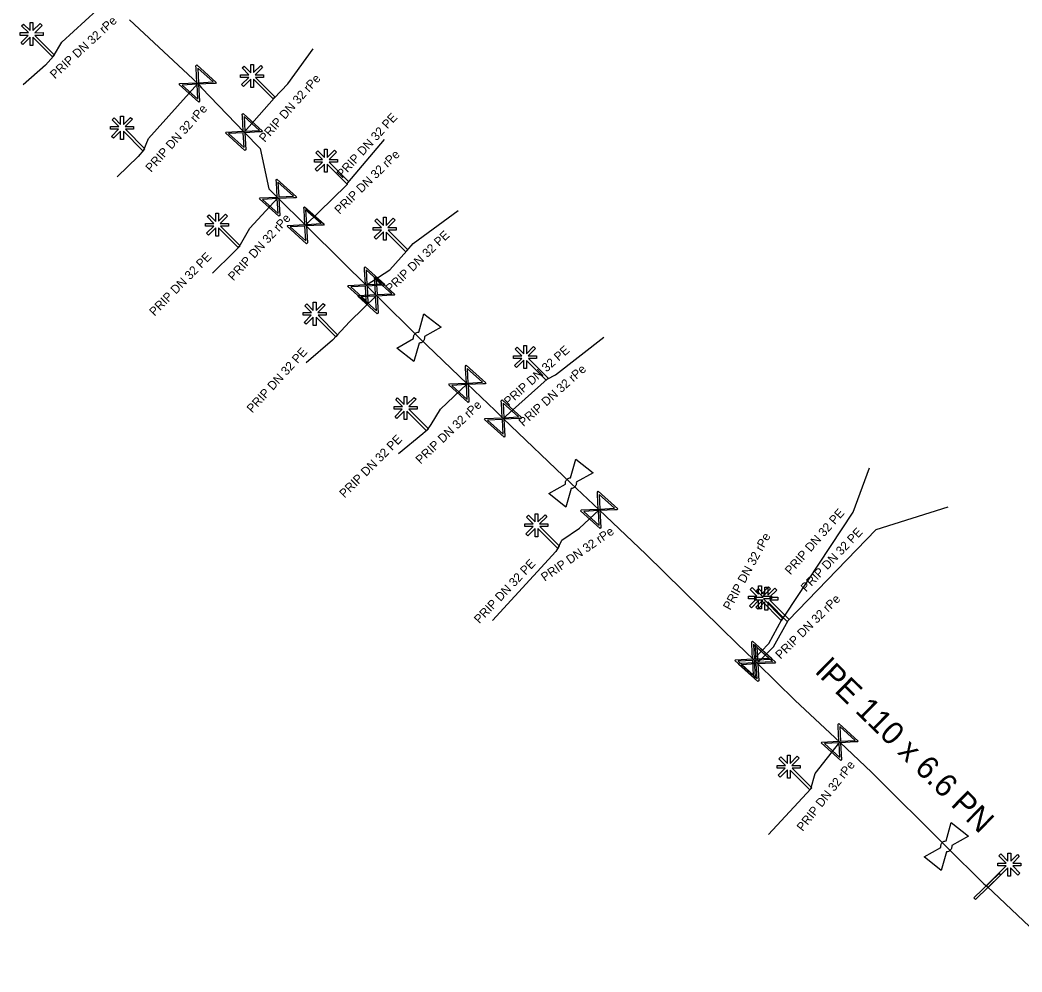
# Model space of a CAD drawing. Extents: x -643842 to -636370, y -1119190 to -1110210.
# Drawn here: x -640918.7 to -640861.5, y -1114875.7 to -1114821.3 of the extents above; entities that cross this region are included whole.
import ezdxf

# ---------------------------------------------------------------- set-up
doc = ezdxf.new("R2010")
doc.units = 0
for name, color, linetype in [('2', 7, 'Continuous'), ('22', 7, 'Continuous'), ('Default', 7, 'Continuous'), ('Level 16', 7, 'Continuous'), ('Level 20', 7, 'Continuous'), ('Level 21', 7, 'Continuous'), ('Level 23', 7, 'Continuous'), ('Level 28', 7, 'Continuous')]:
    doc.layers.add(name, color=color, linetype=linetype)

msp = doc.modelspace()

# ---------------------------------------------------------------- linework, layer by layer
at = {"layer": '2'}
for points in [[(-640918.238, -1114822.055), (-640918.619, -1114821.673), (-640918.508, -1114821.563), (-640918.131, -1114821.941), (-640918.131, -1114821.473), (-640917.974, -1114821.474), (-640917.974, -1114821.939), (-640917.566, -1114821.532), (-640917.456, -1114821.643), (-640917.871, -1114822.057), (-640917.397, -1114822.056), (-640917.397, -1114822.212), (-640917.861, -1114822.212), (-640916.743, -1114823.333), (-640916.854, -1114823.443), (-640917.975, -1114822.319), (-640917.975, -1114822.791), (-640918.131, -1114822.79), (-640918.131, -1114822.316), (-640918.545, -1114822.729), (-640918.656, -1114822.618), (-640918.248, -1114822.212), (-640918.712, -1114822.211), (-640918.712, -1114822.055), (-640918.238, -1114822.055)], [(-640905.648, -1114824.455), (-640906.029, -1114824.073), (-640905.918, -1114823.963), (-640905.541, -1114824.341), (-640905.541, -1114823.873), (-640905.384, -1114823.874), (-640905.384, -1114824.339), (-640904.976, -1114823.932), (-640904.866, -1114824.043), (-640905.281, -1114824.457), (-640904.807, -1114824.456), (-640904.807, -1114824.612), (-640905.271, -1114824.612), (-640904.153, -1114825.733), (-640904.264, -1114825.843), (-640905.385, -1114824.719), (-640905.385, -1114825.191), (-640905.541, -1114825.19), (-640905.541, -1114824.716), (-640905.955, -1114825.129), (-640906.066, -1114825.018), (-640905.658, -1114824.612), (-640906.122, -1114824.611), (-640906.122, -1114824.455), (-640905.648, -1114824.455)], [(-640913.078, -1114827.415), (-640913.459, -1114827.033), (-640913.348, -1114826.923), (-640912.971, -1114827.301), (-640912.971, -1114826.833), (-640912.814, -1114826.834), (-640912.814, -1114827.299), (-640912.406, -1114826.892), (-640912.296, -1114827.003), (-640912.711, -1114827.417), (-640912.237, -1114827.416), (-640912.237, -1114827.572), (-640912.701, -1114827.572), (-640911.583, -1114828.693), (-640911.694, -1114828.803), (-640912.815, -1114827.679), (-640912.815, -1114828.151), (-640912.971, -1114828.15), (-640912.971, -1114827.676), (-640913.385, -1114828.089), (-640913.496, -1114827.978), (-640913.088, -1114827.572), (-640913.552, -1114827.571), (-640913.552, -1114827.415), (-640913.078, -1114827.415)], [(-640901.438, -1114829.295), (-640901.819, -1114828.913), (-640901.708, -1114828.803), (-640901.331, -1114829.181), (-640901.331, -1114828.713), (-640901.174, -1114828.714), (-640901.174, -1114829.179), (-640900.766, -1114828.772), (-640900.656, -1114828.883), (-640901.071, -1114829.297), (-640900.597, -1114829.296), (-640900.597, -1114829.452), (-640901.061, -1114829.452), (-640899.943, -1114830.573), (-640900.054, -1114830.683), (-640901.175, -1114829.559), (-640901.175, -1114830.031), (-640901.331, -1114830.03), (-640901.331, -1114829.556), (-640901.745, -1114829.969), (-640901.856, -1114829.858), (-640901.448, -1114829.452), (-640901.912, -1114829.451), (-640901.912, -1114829.295), (-640901.438, -1114829.295)], [(-640907.648, -1114832.945), (-640908.029, -1114832.563), (-640907.918, -1114832.453), (-640907.541, -1114832.831), (-640907.541, -1114832.363), (-640907.384, -1114832.364), (-640907.384, -1114832.829), (-640906.976, -1114832.422), (-640906.866, -1114832.533), (-640907.281, -1114832.947), (-640906.807, -1114832.946), (-640906.807, -1114833.102), (-640907.271, -1114833.102), (-640906.153, -1114834.223), (-640906.264, -1114834.333), (-640907.385, -1114833.209), (-640907.385, -1114833.681), (-640907.541, -1114833.68), (-640907.541, -1114833.206), (-640907.955, -1114833.619), (-640908.066, -1114833.508), (-640907.658, -1114833.102), (-640908.122, -1114833.101), (-640908.122, -1114832.945), (-640907.648, -1114832.945)], [(-640898.078, -1114833.175), (-640898.459, -1114832.793), (-640898.348, -1114832.683), (-640897.971, -1114833.061), (-640897.971, -1114832.593), (-640897.814, -1114832.594), (-640897.814, -1114833.059), (-640897.406, -1114832.652), (-640897.296, -1114832.763), (-640897.711, -1114833.177), (-640897.237, -1114833.176), (-640897.237, -1114833.332), (-640897.701, -1114833.332), (-640896.583, -1114834.453), (-640896.694, -1114834.563), (-640897.815, -1114833.439), (-640897.815, -1114833.911), (-640897.971, -1114833.91), (-640897.971, -1114833.436), (-640898.385, -1114833.849), (-640898.496, -1114833.738), (-640898.088, -1114833.332), (-640898.552, -1114833.331), (-640898.552, -1114833.175), (-640898.078, -1114833.175)], [(-640902.078, -1114838.035), (-640902.459, -1114837.653), (-640902.348, -1114837.543), (-640901.971, -1114837.921), (-640901.971, -1114837.453), (-640901.814, -1114837.454), (-640901.814, -1114837.919), (-640901.406, -1114837.512), (-640901.296, -1114837.623), (-640901.711, -1114838.037), (-640901.237, -1114838.036), (-640901.237, -1114838.192), (-640901.701, -1114838.192), (-640900.583, -1114839.313), (-640900.694, -1114839.423), (-640901.815, -1114838.299), (-640901.815, -1114838.771), (-640901.971, -1114838.77), (-640901.971, -1114838.296), (-640902.385, -1114838.709), (-640902.496, -1114838.598), (-640902.088, -1114838.192), (-640902.552, -1114838.191), (-640902.552, -1114838.035), (-640902.078, -1114838.035)], [(-640890.068, -1114840.505), (-640890.449, -1114840.123), (-640890.338, -1114840.013), (-640889.961, -1114840.391), (-640889.961, -1114839.923), (-640889.804, -1114839.924), (-640889.804, -1114840.389), (-640889.396, -1114839.982), (-640889.286, -1114840.093), (-640889.701, -1114840.507), (-640889.227, -1114840.506), (-640889.227, -1114840.662), (-640889.691, -1114840.662), (-640888.573, -1114841.783), (-640888.684, -1114841.893), (-640889.805, -1114840.769), (-640889.805, -1114841.241), (-640889.961, -1114841.24), (-640889.961, -1114840.766), (-640890.375, -1114841.179), (-640890.486, -1114841.068), (-640890.078, -1114840.662), (-640890.542, -1114840.661), (-640890.542, -1114840.505), (-640890.068, -1114840.505)], [(-640896.888, -1114843.405), (-640897.269, -1114843.023), (-640897.158, -1114842.913), (-640896.781, -1114843.291), (-640896.781, -1114842.823), (-640896.624, -1114842.824), (-640896.624, -1114843.289), (-640896.216, -1114842.882), (-640896.106, -1114842.993), (-640896.521, -1114843.407), (-640896.047, -1114843.406), (-640896.047, -1114843.562), (-640896.511, -1114843.562), (-640895.393, -1114844.683), (-640895.504, -1114844.793), (-640896.625, -1114843.669), (-640896.625, -1114844.141), (-640896.781, -1114844.14), (-640896.781, -1114843.666), (-640897.195, -1114844.079), (-640897.306, -1114843.968), (-640896.898, -1114843.562), (-640897.362, -1114843.561), (-640897.362, -1114843.405), (-640896.888, -1114843.405)], [(-640889.418, -1114850.105), (-640889.799, -1114849.723), (-640889.688, -1114849.613), (-640889.311, -1114849.991), (-640889.311, -1114849.523), (-640889.154, -1114849.524), (-640889.154, -1114849.989), (-640888.746, -1114849.582), (-640888.636, -1114849.693), (-640889.051, -1114850.107), (-640888.577, -1114850.106), (-640888.577, -1114850.262), (-640889.041, -1114850.262), (-640887.923, -1114851.383), (-640888.034, -1114851.493), (-640889.155, -1114850.369), (-640889.155, -1114850.841), (-640889.311, -1114850.84), (-640889.311, -1114850.366), (-640889.725, -1114850.779), (-640889.836, -1114850.668), (-640889.428, -1114850.262), (-640889.892, -1114850.261), (-640889.892, -1114850.105), (-640889.418, -1114850.105)], [(-640876.658, -1114854.225), (-640877.039, -1114853.843), (-640876.928, -1114853.733), (-640876.551, -1114854.111), (-640876.551, -1114853.643), (-640876.394, -1114853.644), (-640876.394, -1114854.109), (-640875.986, -1114853.702), (-640875.876, -1114853.813), (-640876.291, -1114854.227), (-640875.817, -1114854.226), (-640875.817, -1114854.382), (-640876.281, -1114854.382), (-640875.163, -1114855.503), (-640875.274, -1114855.613), (-640876.395, -1114854.489), (-640876.395, -1114854.961), (-640876.551, -1114854.96), (-640876.551, -1114854.486), (-640876.965, -1114854.899), (-640877.076, -1114854.788), (-640876.668, -1114854.382), (-640877.132, -1114854.381), (-640877.132, -1114854.225), (-640876.658, -1114854.225)], [(-640876.298, -1114854.295), (-640876.679, -1114853.913), (-640876.568, -1114853.803), (-640876.191, -1114854.181), (-640876.191, -1114853.713), (-640876.034, -1114853.714), (-640876.034, -1114854.179), (-640875.626, -1114853.772), (-640875.516, -1114853.883), (-640875.931, -1114854.297), (-640875.457, -1114854.296), (-640875.457, -1114854.452), (-640875.921, -1114854.452), (-640874.803, -1114855.573), (-640874.914, -1114855.683), (-640876.035, -1114854.559), (-640876.035, -1114855.031), (-640876.191, -1114855.03), (-640876.191, -1114854.556), (-640876.605, -1114854.969), (-640876.716, -1114854.858), (-640876.308, -1114854.452), (-640876.772, -1114854.451), (-640876.772, -1114854.295), (-640876.298, -1114854.295)], [(-640875.018, -1114863.895), (-640875.399, -1114863.513), (-640875.288, -1114863.403), (-640874.911, -1114863.781), (-640874.911, -1114863.313), (-640874.754, -1114863.314), (-640874.754, -1114863.779), (-640874.346, -1114863.372), (-640874.236, -1114863.483), (-640874.651, -1114863.897), (-640874.177, -1114863.896), (-640874.177, -1114864.052), (-640874.641, -1114864.052), (-640873.523, -1114865.173), (-640873.634, -1114865.283), (-640874.755, -1114864.159), (-640874.755, -1114864.631), (-640874.911, -1114864.63), (-640874.911, -1114864.156), (-640875.325, -1114864.569), (-640875.436, -1114864.458), (-640875.028, -1114864.052), (-640875.492, -1114864.051), (-640875.492, -1114863.895), (-640875.018, -1114863.895)], [(-640862.165, -1114869.372), (-640861.783, -1114868.991), (-640861.673, -1114869.102), (-640862.051, -1114869.479), (-640861.583, -1114869.479), (-640861.584, -1114869.636), (-640862.049, -1114869.636), (-640861.642, -1114870.044), (-640861.753, -1114870.154), (-640862.167, -1114869.739), (-640862.166, -1114870.213), (-640862.322, -1114870.213), (-640862.322, -1114869.749), (-640863.443, -1114870.867), (-640863.553, -1114870.756), (-640862.429, -1114869.635), (-640862.901, -1114869.635), (-640862.9, -1114869.479), (-640862.426, -1114869.479), (-640862.839, -1114869.065), (-640862.728, -1114868.954), (-640862.322, -1114869.362), (-640862.321, -1114868.898), (-640862.165, -1114868.898), (-640862.165, -1114869.372)]]:
    msp.add_lwpolyline(points, dxfattribs=at)
at = {"layer": 'Default'}
for points in [[(-640896.247, -1114839.529), (-640896.257, -1114839.478), (-640896.249, -1114839.424), (-640896.236, -1114839.34), (-640896.185, -1114839.276), (-640896.134, -1114839.212), (-640896.054, -1114839.179), (-640896.005, -1114839.159), (-640895.952, -1114839.157)], [(-640895.631, -1114839.41), (-640895.622, -1114839.461), (-640895.63, -1114839.514), (-640895.644, -1114839.6), (-640895.695, -1114839.664), (-640895.745, -1114839.728), (-640895.823, -1114839.76), (-640895.874, -1114839.78), (-640895.927, -1114839.782)], [(-640887.577, -1114847.839), (-640887.587, -1114847.788), (-640887.579, -1114847.734), (-640887.566, -1114847.65), (-640887.515, -1114847.586), (-640887.464, -1114847.522), (-640887.384, -1114847.489), (-640887.335, -1114847.469), (-640887.282, -1114847.467)], [(-640886.961, -1114847.72), (-640886.952, -1114847.771), (-640886.96, -1114847.824), (-640886.974, -1114847.91), (-640887.025, -1114847.974), (-640887.075, -1114848.038), (-640887.153, -1114848.07), (-640887.204, -1114848.09), (-640887.257, -1114848.092)], [(-640866.147, -1114868.579), (-640866.157, -1114868.528), (-640866.149, -1114868.474), (-640866.136, -1114868.39), (-640866.085, -1114868.326), (-640866.035, -1114868.262), (-640865.954, -1114868.229), (-640865.905, -1114868.209), (-640865.852, -1114868.207)], [(-640865.532, -1114868.46), (-640865.522, -1114868.511), (-640865.53, -1114868.564), (-640865.544, -1114868.65), (-640865.595, -1114868.714), (-640865.645, -1114868.778), (-640865.723, -1114868.81), (-640865.774, -1114868.83), (-640865.827, -1114868.832)]]:
    msp.add_open_spline(points, degree=3, dxfattribs=at)
at = {"layer": 'Level 16'}
for points in [[(-640908.625, -1114823.901), (-640907.511, -1114824.905), (-640907.555, -1114824.954), (-640907.683, -1114824.957), (-640908.522, -1114825.001), (-640908.471, -1114825.97), (-640908.515, -1114826.019), (-640909.629, -1114825.015), (-640909.585, -1114824.966), (-640908.615, -1114824.918), (-640908.659, -1114824.079), (-640908.669, -1114823.95), (-640908.625, -1114823.901)], [(-640908.571, -1114824.076), (-640908.527, -1114824.913), (-640907.691, -1114824.869), (-640908.571, -1114824.076)], [(-640908.566, -1114825.848), (-640908.61, -1114825.006), (-640909.45, -1114825.05), (-640908.566, -1114825.848)], [(-640905.981, -1114826.67), (-640904.867, -1114827.674), (-640904.911, -1114827.723), (-640905.039, -1114827.726), (-640905.878, -1114827.77), (-640905.827, -1114828.739), (-640905.871, -1114828.788), (-640906.985, -1114827.784), (-640906.941, -1114827.735), (-640905.971, -1114827.687), (-640906.015, -1114826.848), (-640906.025, -1114826.719), (-640905.981, -1114826.67)], [(-640905.927, -1114826.845), (-640905.883, -1114827.682), (-640905.047, -1114827.638), (-640905.927, -1114826.845)], [(-640905.922, -1114828.617), (-640905.966, -1114827.775), (-640906.806, -1114827.819), (-640905.922, -1114828.617)], [(-640904.045, -1114830.426), (-640902.931, -1114831.43), (-640902.975, -1114831.479), (-640903.103, -1114831.482), (-640903.942, -1114831.526), (-640903.891, -1114832.495), (-640903.935, -1114832.544), (-640905.049, -1114831.54), (-640905.005, -1114831.491), (-640904.035, -1114831.443), (-640904.079, -1114830.604), (-640904.089, -1114830.475), (-640904.045, -1114830.426)], [(-640903.991, -1114830.601), (-640903.947, -1114831.438), (-640903.111, -1114831.394), (-640903.991, -1114830.601)], [(-640903.986, -1114832.373), (-640904.03, -1114831.531), (-640904.87, -1114831.575), (-640903.986, -1114832.373)], [(-640902.466, -1114831.993), (-640901.352, -1114832.997), (-640901.396, -1114833.046), (-640901.524, -1114833.049), (-640902.363, -1114833.093), (-640902.312, -1114834.062), (-640902.356, -1114834.111), (-640903.47, -1114833.107), (-640903.426, -1114833.058), (-640902.456, -1114833.01), (-640902.5, -1114832.171), (-640902.51, -1114832.042), (-640902.466, -1114831.993)], [(-640902.412, -1114832.168), (-640902.368, -1114833.005), (-640901.532, -1114832.961), (-640902.412, -1114832.168)], [(-640902.407, -1114833.94), (-640902.451, -1114833.098), (-640903.291, -1114833.142), (-640902.407, -1114833.94)], [(-640899.007, -1114835.423), (-640897.893, -1114836.427), (-640897.937, -1114836.476), (-640898.065, -1114836.479), (-640898.904, -1114836.523), (-640898.853, -1114837.492), (-640898.897, -1114837.541), (-640900.011, -1114836.537), (-640899.967, -1114836.488), (-640898.997, -1114836.44), (-640899.041, -1114835.601), (-640899.051, -1114835.472), (-640899.007, -1114835.423)], [(-640898.953, -1114835.598), (-640898.909, -1114836.435), (-640898.073, -1114836.391), (-640898.953, -1114835.598)], [(-640898.429, -1114835.997), (-640897.315, -1114837.001), (-640897.359, -1114837.05), (-640897.487, -1114837.053), (-640898.326, -1114837.097), (-640898.275, -1114838.066), (-640898.319, -1114838.115), (-640899.433, -1114837.111), (-640899.389, -1114837.062), (-640898.419, -1114837.014), (-640898.463, -1114836.175), (-640898.473, -1114836.046), (-640898.429, -1114835.997)], [(-640898.375, -1114836.172), (-640898.331, -1114837.009), (-640897.495, -1114836.965), (-640898.375, -1114836.172)], [(-640898.948, -1114837.37), (-640898.992, -1114836.528), (-640899.832, -1114836.572), (-640898.948, -1114837.37)], [(-640898.37, -1114837.944), (-640898.414, -1114837.102), (-640899.254, -1114837.146), (-640898.37, -1114837.944)], [(-640893.241, -1114841.05), (-640892.127, -1114842.054), (-640892.171, -1114842.103), (-640892.299, -1114842.106), (-640893.138, -1114842.15), (-640893.087, -1114843.119), (-640893.131, -1114843.168), (-640894.245, -1114842.164), (-640894.201, -1114842.115), (-640893.231, -1114842.067), (-640893.275, -1114841.228), (-640893.285, -1114841.099), (-640893.241, -1114841.05)], [(-640893.187, -1114841.225), (-640893.143, -1114842.062), (-640892.307, -1114842.018), (-640893.187, -1114841.225)], [(-640893.182, -1114842.997), (-640893.226, -1114842.155), (-640894.066, -1114842.199), (-640893.182, -1114842.997)], [(-640891.195, -1114843.031), (-640890.081, -1114844.035), (-640890.125, -1114844.084), (-640890.253, -1114844.087), (-640891.092, -1114844.131), (-640891.041, -1114845.1), (-640891.085, -1114845.149), (-640892.199, -1114844.145), (-640892.155, -1114844.096), (-640891.185, -1114844.048), (-640891.229, -1114843.209), (-640891.239, -1114843.08), (-640891.195, -1114843.031)], [(-640891.141, -1114843.206), (-640891.097, -1114844.043), (-640890.261, -1114843.999), (-640891.141, -1114843.206)], [(-640891.136, -1114844.978), (-640891.18, -1114844.136), (-640892.02, -1114844.18), (-640891.136, -1114844.978)], [(-640885.712, -1114848.245), (-640884.598, -1114849.249), (-640884.642, -1114849.298), (-640884.77, -1114849.301), (-640885.609, -1114849.345), (-640885.558, -1114850.314), (-640885.602, -1114850.363), (-640886.716, -1114849.359), (-640886.672, -1114849.31), (-640885.702, -1114849.262), (-640885.746, -1114848.423), (-640885.756, -1114848.294), (-640885.712, -1114848.245)], [(-640885.658, -1114848.42), (-640885.614, -1114849.257), (-640884.778, -1114849.213), (-640885.658, -1114848.42)], [(-640885.653, -1114850.192), (-640885.697, -1114849.35), (-640886.537, -1114849.394), (-640885.653, -1114850.192)], [(-640876.904, -1114856.796), (-640875.79, -1114857.8), (-640875.834, -1114857.849), (-640875.962, -1114857.852), (-640876.801, -1114857.896), (-640876.75, -1114858.865), (-640876.794, -1114858.914), (-640877.908, -1114857.91), (-640877.864, -1114857.861), (-640876.894, -1114857.813), (-640876.938, -1114856.974), (-640876.948, -1114856.845), (-640876.904, -1114856.796)], [(-640876.85, -1114856.971), (-640876.806, -1114857.808), (-640875.97, -1114857.764), (-640876.85, -1114856.971)], [(-640876.699, -1114856.996), (-640875.585, -1114858), (-640875.629, -1114858.049), (-640875.757, -1114858.052), (-640876.596, -1114858.096), (-640876.545, -1114859.065), (-640876.589, -1114859.114), (-640877.703, -1114858.11), (-640877.659, -1114858.061), (-640876.689, -1114858.013), (-640876.733, -1114857.174), (-640876.743, -1114857.045), (-640876.699, -1114856.996)], [(-640876.645, -1114857.171), (-640876.601, -1114858.008), (-640875.765, -1114857.964), (-640876.645, -1114857.171)], [(-640876.845, -1114858.743), (-640876.889, -1114857.901), (-640877.729, -1114857.945), (-640876.845, -1114858.743)], [(-640876.64, -1114858.943), (-640876.684, -1114858.101), (-640877.524, -1114858.145), (-640876.64, -1114858.943)], [(-640871.975, -1114861.501), (-640870.861, -1114862.505), (-640870.905, -1114862.554), (-640871.033, -1114862.557), (-640871.872, -1114862.601), (-640871.821, -1114863.57), (-640871.865, -1114863.619), (-640872.979, -1114862.615), (-640872.935, -1114862.566), (-640871.965, -1114862.518), (-640872.009, -1114861.679), (-640872.019, -1114861.55), (-640871.975, -1114861.501)], [(-640871.921, -1114861.676), (-640871.877, -1114862.513), (-640871.041, -1114862.469), (-640871.921, -1114861.676)], [(-640871.916, -1114863.448), (-640871.96, -1114862.606), (-640872.8, -1114862.65), (-640871.916, -1114863.448)], [(-640862.739, -1114870.159), (-640864.174, -1114871.551), (-640864.261, -1114871.461), (-640862.826, -1114870.069), (-640862.739, -1114870.159)]]:
    msp.add_lwpolyline(points, dxfattribs=at)
at = {"layer": 'Level 21'}
for points in [[(-640912.47, -1114821.32), (-640908.57, -1114824.96), (-640908.35, -1114825.21), (-640905.926, -1114827.729), (-640905.01, -1114828.68), (-640904.51, -1114830.97), (-640903.99, -1114831.485), (-640902.411, -1114833.052), (-640900.25, -1114835.195), (-640898.952, -1114836.482), (-640898.374, -1114837.056), (-640895.94, -1114839.47), (-640893.186, -1114842.109), (-640891.6, -1114843.63), (-640891.14, -1114844.09), (-640887.265, -1114847.779), (-640885.657, -1114849.304), (-640883, -1114851.84), (-640878.71, -1114856.034), (-640877.78, -1114856.945), (-640876.849, -1114857.855), (-640876.644, -1114858.055), (-640874.46, -1114860.19), (-640871.92, -1114862.56), (-640870.09, -1114864.31), (-640865.84, -1114868.52), (-640863.69, -1114870.66), (-640863.5, -1114870.81)], [(-640863.5, -1114870.81), (-640857.28, -1114876.69), (-640857.1, -1114877.12), (-640858.78, -1114880.5), (-640858.95, -1114880.85)]]:
    msp.add_lwpolyline(points, dxfattribs=at)
at = {"layer": 'Level 23'}
for points in [[(-640916.8, -1114823.39), (-640916.33, -1114822.59), (-640913.662, -1114820.139)], [(-640904.21, -1114825.79), (-640903.422, -1114824.972), (-640901.984, -1114822.972)], [(-640916.8, -1114823.39), (-640917.251, -1114823.921), (-640918.533, -1114825.045)], [(-640911.64, -1114828.75), (-640911.38, -1114828.1), (-640908.57, -1114824.96)], [(-640905.926, -1114827.729), (-640904.21, -1114825.79)], [(-640900, -1114830.63), (-640897.914, -1114828.15)], [(-640911.64, -1114828.75), (-640911.967, -1114829.13), (-640913.169, -1114830.297)], [(-640902.411, -1114833.052), (-640900.09, -1114830.78), (-640900.02, -1114830.71), (-640900, -1114830.63)], [(-640906.21, -1114834.28), (-640905.59, -1114833.22), (-640903.99, -1114831.485)], [(-640896.64, -1114834.51), (-640896.275, -1114834.102), (-640893.703, -1114832.213)], [(-640906.21, -1114834.28), (-640906.532, -1114834.604), (-640907.734, -1114835.796)], [(-640898.952, -1114836.482), (-640897.6, -1114835.59), (-640896.64, -1114834.51)], [(-640900.64, -1114839.37), (-640899.89, -1114838.55), (-640898.374, -1114837.056)], [(-640900.64, -1114839.37), (-640900.885, -1114839.612), (-640902.385, -1114840.91)], [(-640888.63, -1114841.84), (-640888.143, -1114841.591), (-640885.387, -1114839.442)], [(-640895.45, -1114844.74), (-640895.25, -1114844.43), (-640894.71, -1114843.56), (-640893.186, -1114842.109)], [(-640891.14, -1114844.09), (-640888.63, -1114841.84)], [(-640895.45, -1114844.74), (-640895.714, -1114844.972), (-640897.103, -1114846.097)], [(-640875.22, -1114855.56), (-640875.031, -1114855.32), (-640871.162, -1114849.427), (-640870.221, -1114846.908)], [(-640887.98, -1114851.44), (-640887.79, -1114851.04), (-640886.78, -1114850.34), (-640885.657, -1114849.304)], [(-640874.86, -1114855.63), (-640869.844, -1114850.422), (-640865.736, -1114849.122)], [(-640887.98, -1114851.44), (-640888.137, -1114851.675), (-640891.739, -1114855.624)], [(-640876.849, -1114857.855), (-640875.97, -1114856.94), (-640875.22, -1114855.56)], [(-640876.644, -1114858.055), (-640875.7, -1114857.12), (-640874.86, -1114855.63)], [(-640873.58, -1114865.23), (-640873.33, -1114864.35), (-640871.92, -1114862.56)], [(-640873.58, -1114865.23), (-640875.99, -1114867.841)]]:
    msp.add_lwpolyline(points, dxfattribs=at)
at = {"layer": 'Level 28'}
for points in [[(-640895.952, -1114839.157), (-640895.655, -1114838.102)], [(-640895.655, -1114838.102), (-640894.675, -1114838.877), (-640895.631, -1114839.41)], [(-640895.927, -1114839.782), (-640896.224, -1114840.838), (-640897.205, -1114840.063), (-640896.247, -1114839.529)], [(-640887.282, -1114847.467), (-640886.985, -1114846.412)], [(-640886.985, -1114846.412), (-640886.005, -1114847.187), (-640886.961, -1114847.72)], [(-640887.257, -1114848.092), (-640887.554, -1114849.148), (-640888.535, -1114848.373), (-640887.577, -1114847.839)], [(-640865.852, -1114868.207), (-640865.556, -1114867.152)], [(-640865.556, -1114867.152), (-640864.575, -1114867.927), (-640865.532, -1114868.46)], [(-640865.827, -1114868.832), (-640866.124, -1114869.888), (-640867.105, -1114869.113), (-640866.147, -1114868.579)]]:
    msp.add_lwpolyline(points, dxfattribs=at)

# ---------------------------------------------------------------- texts
at = {"layer": '22'}
for s, rotation, p in [('PRIP DN 32 rPe', 42.5726, (-640916.724, -1114824.725)), ('PRIP DN 32 rPe', 48.4914, (-640904.745, -1114828.346)), ('PRIP DN 32 rPe', 48.1745, (-640911.234, -1114830.057)), ('PRIP DN 32 PE', 47.4697, (-640900.326, -1114830.404)), ('PRIP DN 32 rPe', 44.3888, (-640900.472, -1114832.462)), ('PRIP DN 32 rPe', 47.318, (-640906.526, -1114836.261)), ('PRIP DN 32 PE', 43.7943, (-640897.557, -1114836.938)), ('PRIP DN 32 PE', 45.6707, (-640911.036, -1114838.273)), ('PRIP DN 32 PE', 47.6032, (-640905.455, -1114843.804)), ('PRIP DN 32 PE', 41.6964, (-640890.821, -1114843.39)), ('PRIP DN 32 rPe', 41.8735, (-640889.976, -1114844.579)), ('PRIP DN 32 rPe', 43.5944, (-640895.845, -1114846.722)), ('PRIP DN 32 PE', 45.0326, (-640900.19, -1114848.657)), ('PRIP DN 32 PE', 48.6642, (-640874.733, -1114853.049)), ('PRIP DN 32 rPe', 34.7246, (-640888.757, -1114853.415)), ('PRIP DN 32 rPe', 61.4769, (-640878.176, -1114855.068)), ('PRIP DN 32 PE', 46.1035, (-640873.846, -1114854.019)), ('PRIP DN 32 PE', 46.5128, (-640892.492, -1114855.833)), ('PRIP DN 32 rPe', 44.7256, (-640875.301, -1114857.862)), ('PRIP DN 32 rPe', 51.7722, (-640874.033, -1114867.696))]:
    msp.add_text(s, height=0.5, rotation=rotation, dxfattribs=at).set_placement(p)
at = {"layer": 'Level 20'}
msp.add_text('lPE 110 x 6.6 PN ', height=1.3, rotation=315.65, dxfattribs=at).set_placement((-640873.374, -1114858.59))

doc.saveas('drawing.dxf')
